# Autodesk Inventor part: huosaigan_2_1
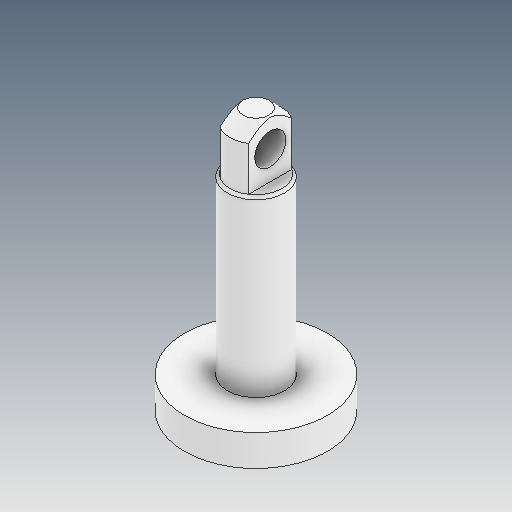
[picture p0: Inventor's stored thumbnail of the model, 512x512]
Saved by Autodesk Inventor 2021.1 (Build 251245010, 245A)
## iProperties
Created: 2021-05
Part Number: huosaigan_2_1
Material: Ogólny
Document SubType Name: Modeling
Designer: user
Density: 1 g/cm^3
Appearance: Domyślna
Author: user
Revision Number: ÈÎºÎ
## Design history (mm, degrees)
feature "ÊäÈë1"
node "Bryła1"
